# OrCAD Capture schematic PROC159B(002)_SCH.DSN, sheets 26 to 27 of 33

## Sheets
26 16. SOC-IO Interfaces: size C; title: SOC-IO Interfaces
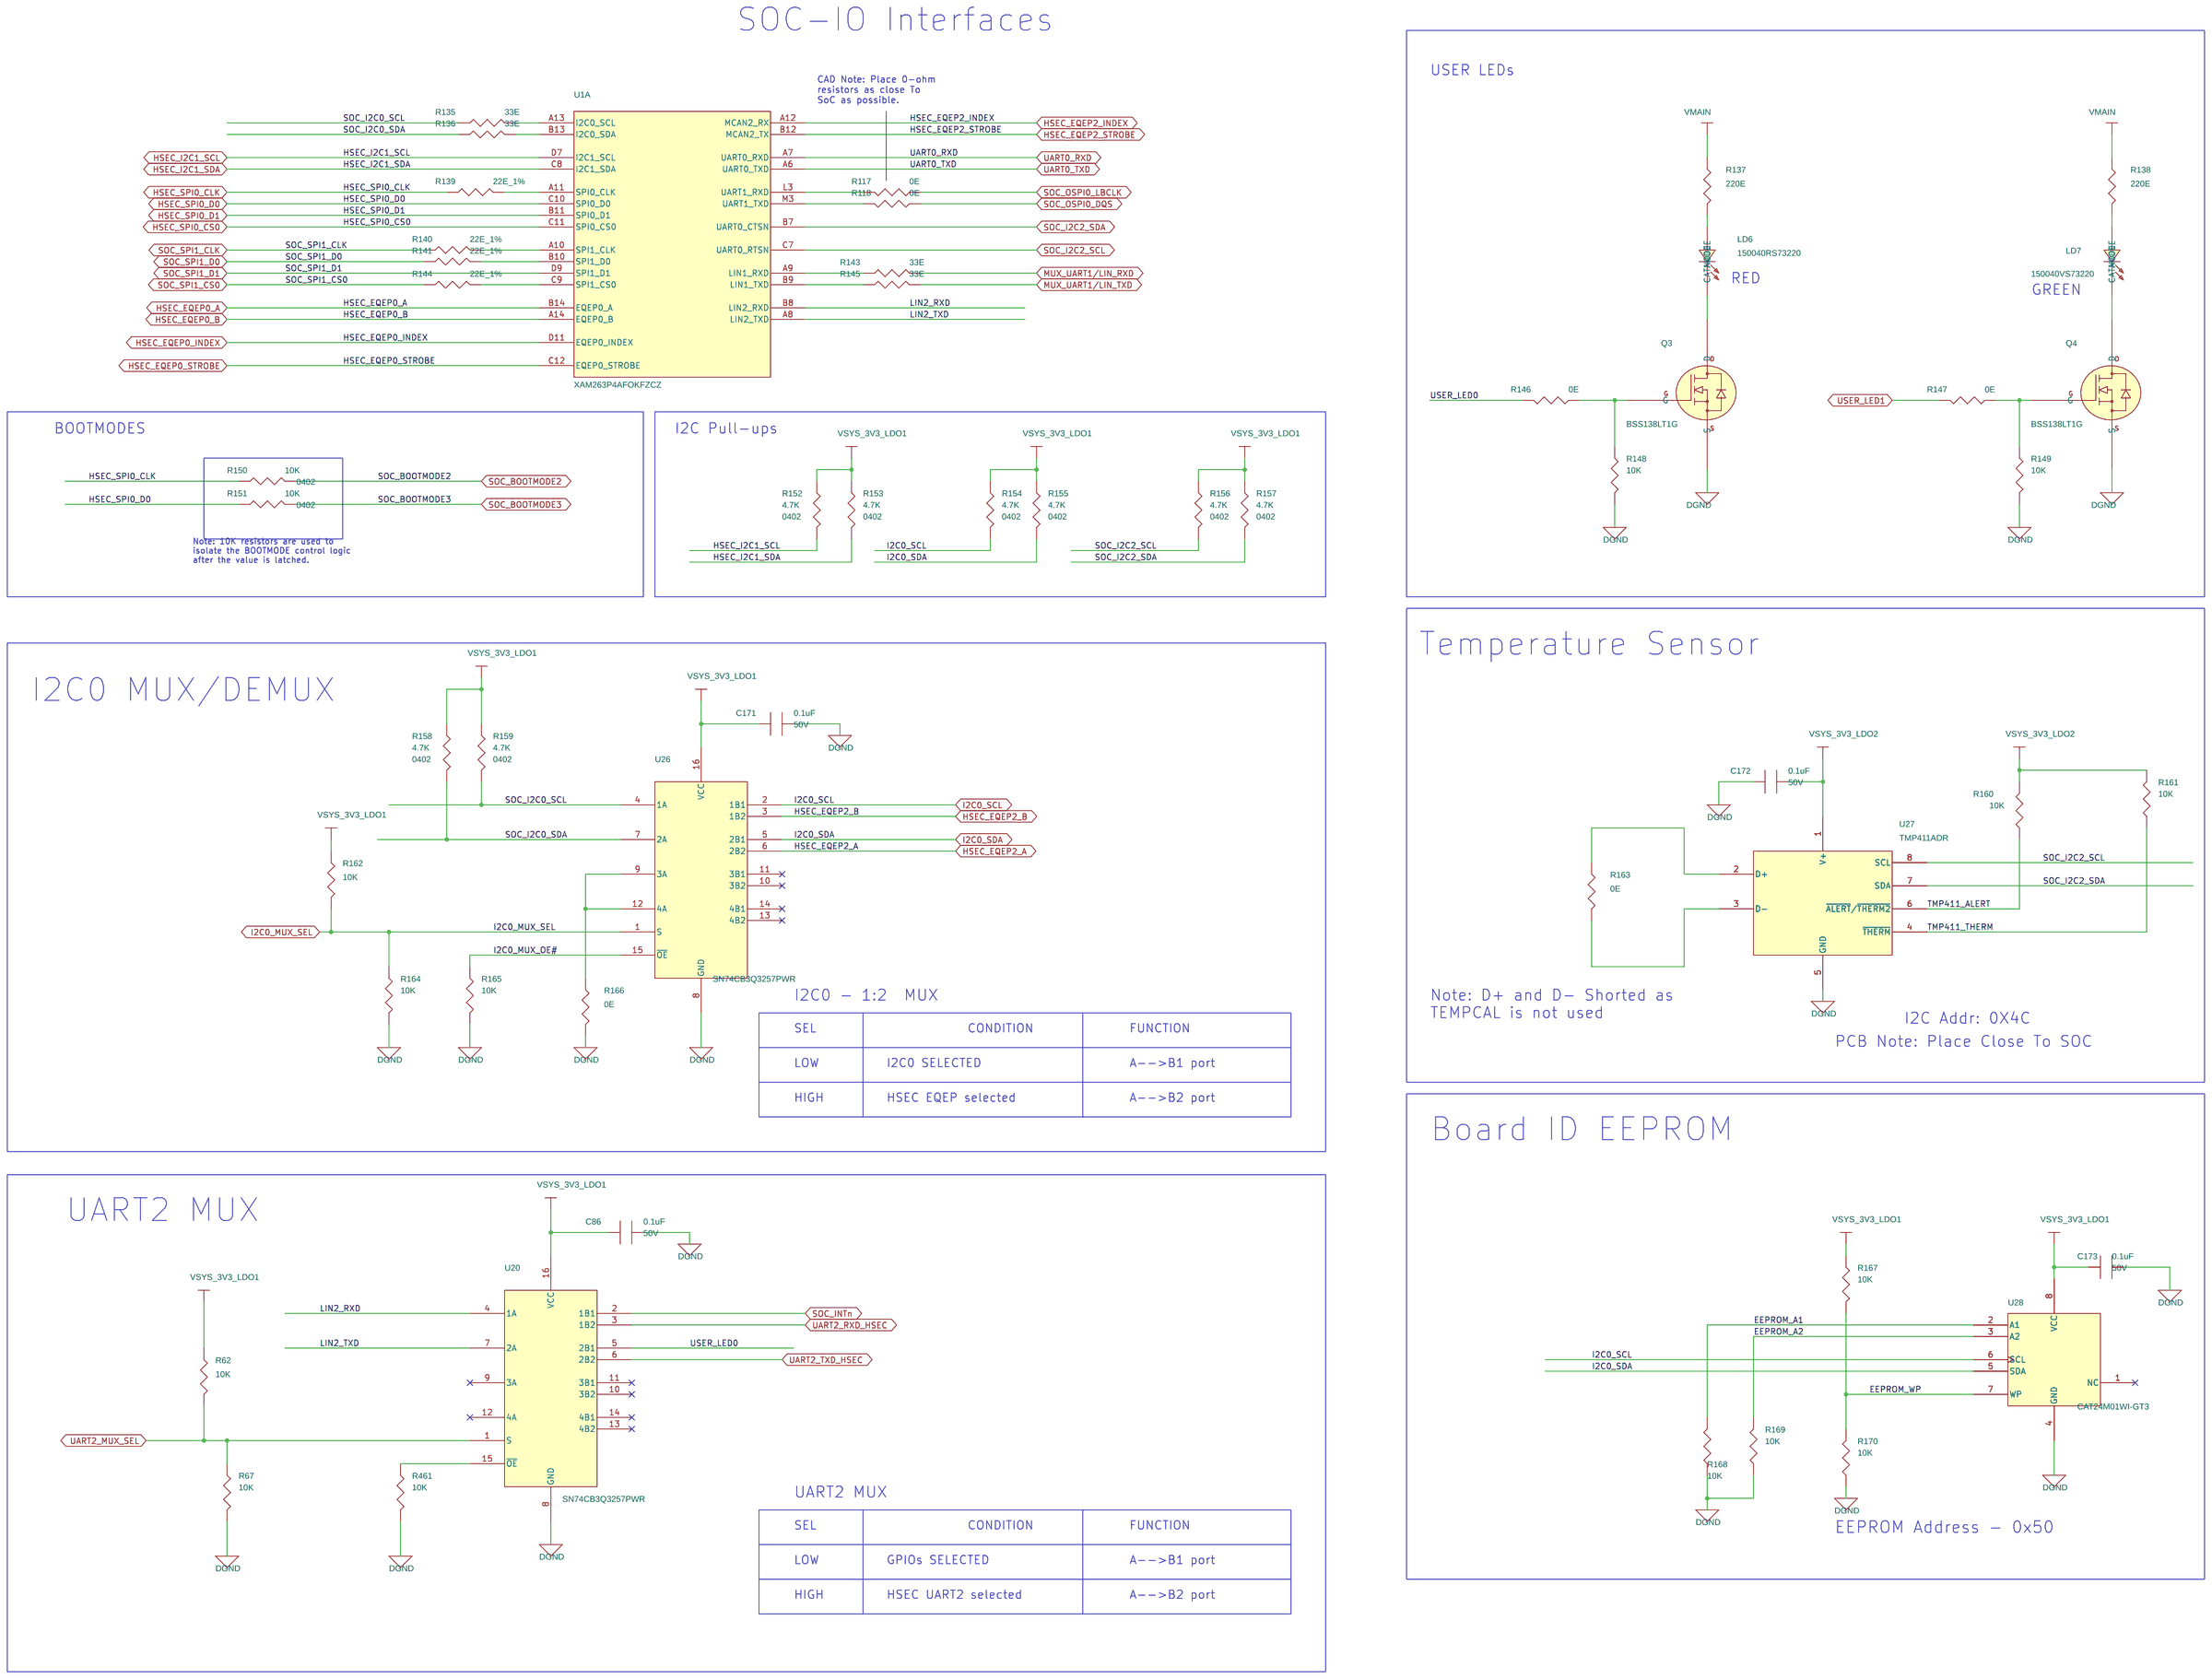
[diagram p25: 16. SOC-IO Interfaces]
27 17. SOC-JTAG, RESET and CLK: size C; title: SOC JTAG, RESET and CLKS
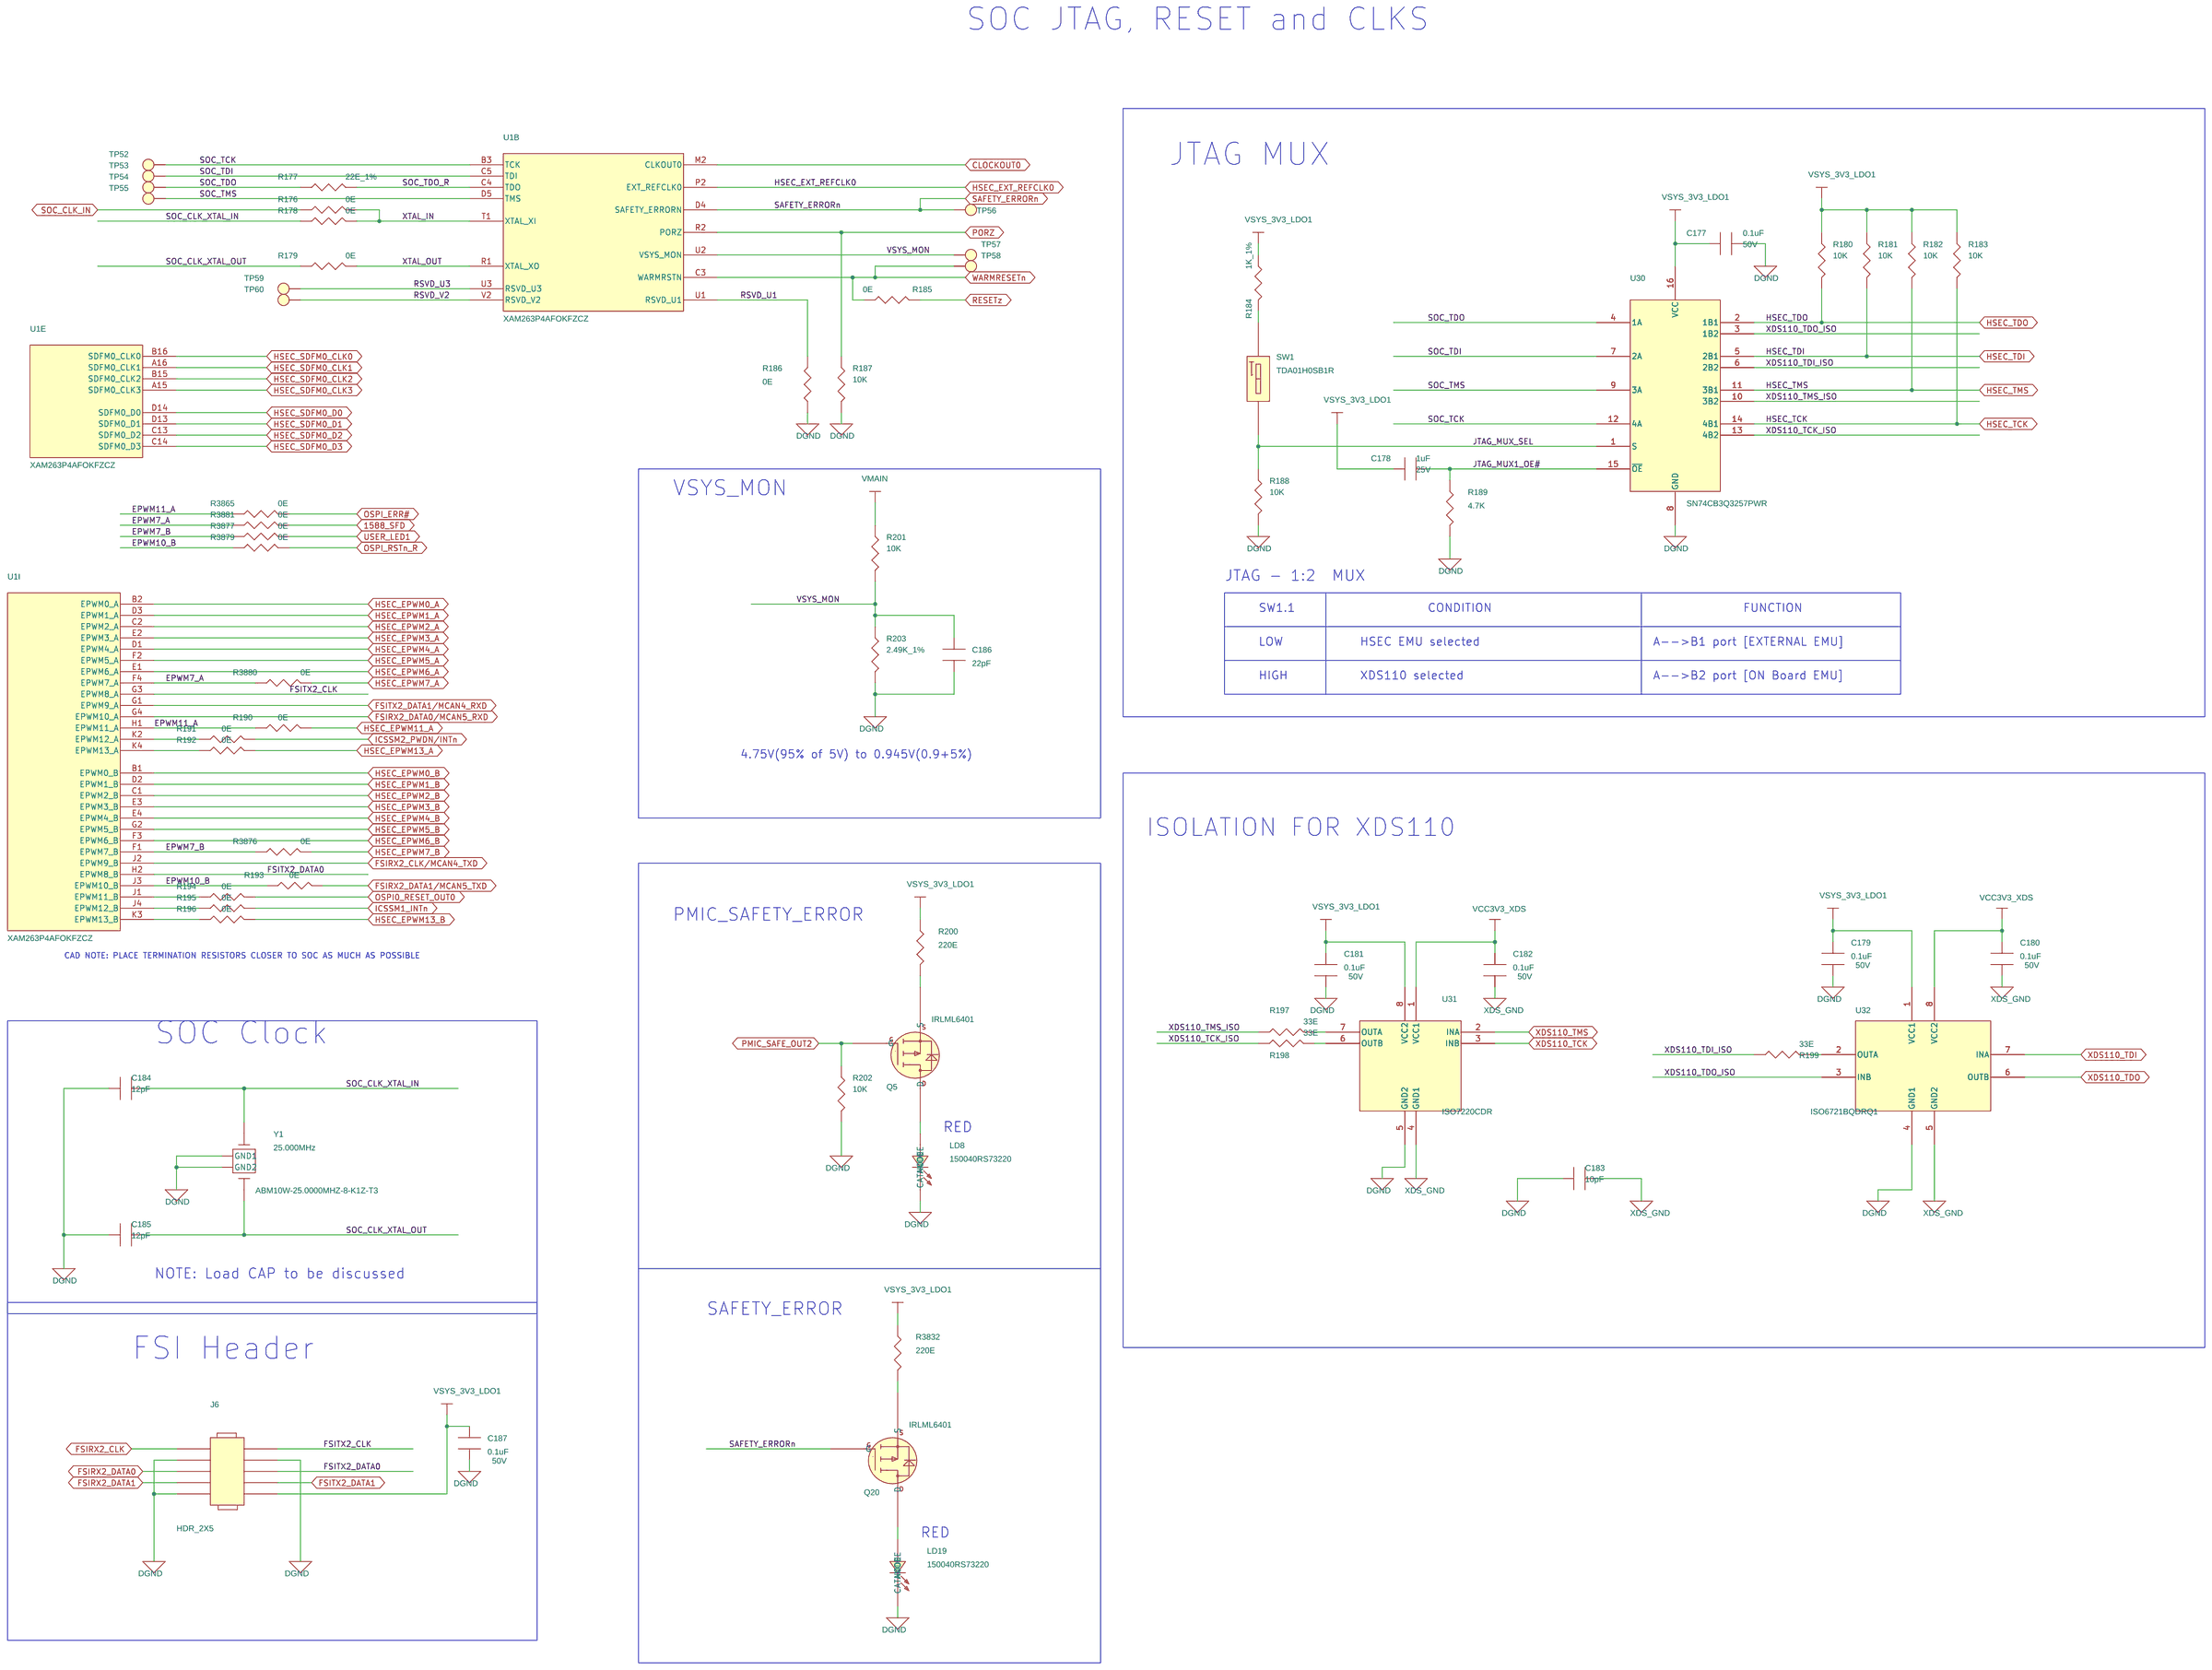
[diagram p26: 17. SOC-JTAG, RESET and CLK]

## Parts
sheet 16. SOC-IO Interfaces
C86  0.1uF  [CAP0402_0-75]
C171  0.1uF  [CAP0402_0-75]
C172  0.1uF  [CAP0402_0-75]
C173  0.1uF  [CAP0402_0-75]
LD6  150040RS73220  [LED_150040GS73220_40X20_SMD_0-4]
LD7  150040VS73220  [LED_150040GS73220_40X20_SMD_0-4]
Q3  BSS138LT1G  [SOT23-123_1-2]
Q4  BSS138LT1G  [SOT23-123_1-2]
R62  10K  [RES0402_0-5]
R67  10K  [RES0402_0-5]
R117  0E  [RES0402_0-5]
R118  0E  [RES0402_0-5]
R135  33E  [RES0402_0-5]
R136  33E  [RES0402_0-5]
R137  220E  [RES0402_0-5]
R138  220E  [RES0402_0-5]
R139  22E_1%  [RES0402_0-5]
R140  22E_1%  [RES0402_0-5]
R141  22E_1%  [RES0402_0-5]
R143  33E  [RES0402_0-5]
R144  22E_1%  [RES0402_0-5]
R145  33E  [RES0402_0-5]
R146  0E  [RES0402_0-5]
R147  0E  [RES0402_0-5]
R148  10K  [RES0402_0-5]
R149  10K  [RES0402_0-5]
R150  10K  [RES0402_0-5]
R151  10K  [RES0402_0-5]
R152  4.7K  [RES0402_0-5]
R153  4.7K  [RES0402_0-5]
R154  4.7K  [RES0402_0-5]
R155  4.7K  [RES0402_0-5]
R156  4.7K  [RES0402_0-5]
R157  4.7K  [RES0402_0-5]
R158  4.7K  [RES0402_0-5]
R159  4.7K  [RES0402_0-5]
R160  10K  [RES0402_0-5]
R161  10K  [RES0402_0-5]
R162  10K  [RES0402_0-5]
R163  0E  [RES0402_0-5]
R164  10K  [RES0402_0-5]
R165  10K  [RES0402_0-5]
R166  0E  [RES0402_0-5]
R167  10K  [RES0402_0-5]
R168  10K  [RES0402_0-5]
R169  10K  [RES0402_0-5]
R170  10K  [RES0402_0-5]
R461  10K  [RES0402_0-5]
U20  SN74CB3Q3257PWR  [TSSOP16_25-59_205X180]
U26  SN74CB3Q3257PWR  [TSSOP16_25-59_205X180]
U27  TMP411ADR  [SOIC8_1-8]
U28  CAT24M01WI-GT3  [SOIC8_1-8]
sheet 17. SOC-JTAG, RESET and CLK
C177  0.1uF  [CAP0402_0-75]
C178  1uF  [CAP0402_0-75]
C179  0.1uF  [CAP0402_0-75]
C180  0.1uF  [CAP0402_0-75]
C181  0.1uF  [CAP0402_0-75]
C182  0.1uF  [CAP0402_0-75]
C183  10pF  [CAP1812_1-25]
C184  12pF  [CAP0402_0-75]
C185  12pF  [CAP0402_0-75]
C186  22pF  [CAP0201_0-5]
C187  0.1uF  [CAP0402_0-75]
J6  HDR_2X5  [HDR_2X5_61301021121_S_T_8-6]
LD8  150040RS73220  [LED_150040GS73220_40X20_SMD_0-4]
LD19  150040RS73220  [LED_150040GS73220_40X20_SMD_0-4]
Q5  IRLML6401  [TO_SOT23-123]
Q20  IRLML6401  [TO_SOT23-123]
R176  0E  [RES0402_0-5]
R177  22E_1%  [RES0402_0-5]
R178  0E  [RES0402_0-5]
R179  0E  [RES0402_0-5]
R180  10K  [RES0402_0-5]
R181  10K  [RES0402_0-5]
R182  10K  [RES0402_0-5]
R183  10K  [RES0402_0-5]
R184  1K_1%  [RES0402_0-5]
R185  0E  [RES0402_0-5]
R186  0E  [RES0402_0-5]
R187  10K  [RES0402_0-5]
R188  10K  [RES0402_0-5]
R189  4.7K  [RES0402_0-5]
R190  0E  [RES0402_0-5]
R191  0E  [RES0402_0-5]
R192  0E  [RES0402_0-5]
R193  0E  [RES0402_0-5]
R194  0E  [RES0402_0-5]
R195  0E  [RES0402_0-5]
R196  0E  [RES0402_0-5]
R197  33E  [RES0402_0-5]
R198  33E  [RES0402_0-5]
R199  33E  [RES0402_0-5]
R200  220E  [RES0402_0-5]
R201  10K  [RES0402_0-5]
R202  10K  [RES0402_0-5]
R203  2.49K_1%  [RES0402_0-5]
R3832  220E  [RES0402_0-5]
R3865  0E  [RES0402_0-5]
R3876  0E  [RES0402_0-5]
R3877  0E  [RES0402_0-5]
R3879  0E  [RES0402_0-5]
R3880  0E  [RES0402_0-5]
R3881  0E  [RES0402_0-5]
SW1  TDA01H0SB1R  [SW_TDA01H0S_240X90_SMD_2-3]
TP52  TP40_SMD  [TP40_SMD]
TP53  TP40_SMD  [TP40_SMD]
TP54  TP40_SMD  [TP40_SMD]
TP55  TP40_SMD  [TP40_SMD]
TP56  TP40_SMD  [TP40_SMD]
TP57  TP40_SMD  [TP40_SMD]
TP58  TP40_SMD  [TP40_SMD]
TP59  TP40_SMD  [TP40_SMD]
TP60  TP40_SMD  [TP40_SMD]
U30  SN74CB3Q3257PWR  [TSSOP16_25-59_205X180]
U31  ISO7220CDR  [SOIC8]
U32  ISO6721BQDRQ1  [SOIC8_1-8]
Y1  25.000MHz  [XTAL4_ABM10W_100X80_SMD_0-6]
sheet 19. SOC-ICSS DP8386(Indust)
U1  XAM263P4AFOKFZCZ  [BGA324_31-49_590X590_1-4]  (sections A,B,C,D,E,F,G,H,I,J,K,L,M)

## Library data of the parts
C86 C171 C172 C177 C179-C182 C187 = CAP: CAP CERAMIC 0.1uF 50V 10% X7R 0402; Automotive Alternate_mfr_name: TDK; Automotive Alternate_mfr_part_number: CGA2B3X7R1H104K050BB; Chkd/date: MANIRAJA/261020; Crtd /date: ALVY/211020; Custom_Duty: 15%; Customs_HS_Code: 85322990; Direct Alternate_mfr_name: TDK; Direct Alternate_mfr_part_number: C1005X7R1H104K050BE; Distributor_name: DIGIKEY; Distributor_part_number: 490-10700-1-ND; Footprint Path: Y:\MIS_DATABASE\Library\ALTIUM_TOOL\PCB_FOOTPRINTS\Altium_Footprint_Lib.PcbLib; Height: 0.55MM; Library Path: Y:\MIS_DATABASE\Library\ALTIUM_TOOL\SCHEMATICS_PARTS\MS_DISCRETE_Library.schlib; Mfr_name: MURATA; Mfr_part_number: GRM155R71H104KE14D; Mistral Part No: 120011100014-R; Package: 0402; Part_type: CAPACITORS\CERAMIC; Project: J7_CP; RoHS: RoHS; Temperature: -55°C+125°C; Tolerance: 10%; Voltage: 50V; Wattage: NA; Weight: 3.1mg; Datasheet: Y:\MIS_DATABASE\DATASHEETS\CAPACITORS\GRM155R71H104KE14.PDF
C173 = CAP: CAP CERAMIC 0.1uF 50V 10% X7R 0402; Automotive Alternate_mfr_name: TDK; Automotive Alternate_mfr_part_number: CGA2B1X7R1C104K050BC; Chkd/date: MANIRAJA/261020; Crtd /date: ALVY/211020; Custom_Duty: 15%; Customs_HS_Code: 85322990; Direct Alternate_mfr_name: MURATA; Direct Alternate_mfr_part_number: GCM155R71C104JA55D; Distributor_name: DIGIKEY; Distributor_part_number: 490-10700-1-ND; Footprint Path: Y:\MIS_DATABASE\Library\ALTIUM_TOOL\PCB_FOOTPRINTS\Altium_Footprint_Lib.PcbLib; Height: 0.55MM; Library Path: Y:\MIS_DATABASE\Library\ALTIUM_TOOL\SCHEMATICS_PARTS\MS_DISCRETE_Library.schlib; Mfr_name: MURATA; Mfr_part_number: GRM155R71H104KE14D; Mistral Part No: 120011100014-R; Package: 0402; Part_type: CAPACITORS\CERAMIC; Project: J7_CP; RoHS: RoHS; Temperature: -55°C+125°C; Tolerance: 10%; Voltage: 50V; Wattage: NA; Weight: 3.1mg; Datasheet: Y:\MIS_DATABASE\DATASHEETS\CAPACITORS\GRM155R71H104KE14.PDF
LD6 LD8 LD19 = DIODE_LED: DIODE LED RED SMD; Chkd/date: MANIRAJA/100920; Crtd /date: ALVY/100920; Custom_Duty: 24%; Customs_HS_Code: 85439000; Distributor_name: DIGIKEY; Distributor_part_number: 732-13422-1-ND; Footprint Path: Y:\MIS_DATABASE\Library\ALTIUM_TOOL\PCB_FOOTPRINTS\Altium_Footprint_Lib.PcbLib; Height: 0.35MM; Library Path: Y:\MIS_DATABASE\Library\ALTIUM_TOOL\SCHEMATICS_PARTS\MS_OPTO_Library.schlib; Mfr_name: WURTH ELECTRONICS; Mistral Part No: 130020090020-R; Package: SMD; Part_type: OPTO\LED; Project: AM64X_SKEVM; RoHS: RoHS; Temperature: -40°C+85°C; Tolerance: NA; Voltage: NA; Wattage: NA; Weight: 29.3mg; Datasheet: Y:\MIS_DATABASE\DATASHEETS\DISCRETES\LEDS\150040RS73220.PDF
LD7 = DIODE_LED: DIODE LED BRIGHT GREEN SMD; Chkd/date: MANIRAJA/261120; Crtd /date: ALVY/261120; Custom_Duty: 24%; Customs_HS_Code: 85439000; Distributor_name: DIGIKEY; Distributor_part_number: 732-13425-1-ND; Footprint Path: Y:\MIS_DATABASE\Library\ALTIUM_TOOL\PCB_FOOTPRINTS\Altium_Footprint_Lib.PcbLib; Height: 0.35MM; Library Path: Y:\MIS_DATABASE\Library\ALTIUM_TOOL\SCHEMATICS_PARTS\MS_OPTO_Library.schlib; Mfr_name: WURTH ELECTRONIK; Mistral Part No: 130020110071-R; Package: SMD; Part_type: OPTO\LED; Project: AM64X_SKEVM; RoHS: RoHS; Temperature: -40°C+85°C; Tolerance: NA; Voltage: NA; Wattage: NA; Weight: 29.3mg; Datasheet: Y:\MIS_DATABASE\DATASHEETS\DISCRETES\LEDS\150040VS73220.PDF
Q3 Q4 = MOSFET_BSS138W: IC MOSFET N-CHANNEL 50V 200mA SOT23-3; Chkd/date: MANIRAJA/250219; Crtd /date: JEBRAN/060416; Custom_Duty: 15%; Customs_HS_Code: 85423100; Distributor_name: DIGIKEY; Distributor_part_number: BSS138LT1GOSCT-ND; Footprint Path: Y:\MIS_DATABASE\Library\ALTIUM_TOOL\PCB_FOOTPRINTS\Altium_Footprint_Lib.PcbLib; Height: 1.11MM; Library Path: Y:\MIS_DATABASE\Library\ALTIUM_TOOL\SCHEMATICS_PARTS\MS_MOSFET_Library.schlib; Mfr_name: ON SEMICONDUCTOR; Mistral Part No: 142016040001-R; Package: SOT23-3; Part_type: ICS\POWER\MOSFET; Project: LRDE_ABCM; RoHS: RoHS; Temperature: -55°C+150°C; Tolerance: NA; Voltage: NA; Wattage: NA; Weight: 8mg; Datasheet: Y:\MIS_DATABASE\DATASHEETS\DISCRETES\TRANSISTORS_FETS\BSS138LT1G.PDF
R62 R150 R151 R162 R168-R170 = RESISTOR: RES 10K 1/16W 5% 0402; Chkd/date: VASANTHA/061216; Crtd /date: MAZHAR/230805; Custom_Duty: 15%; Customs_HS_Code: 85332119; Distributor_name: DIGIKEY; Distributor_part_number: 311-10KJRCT-ND; Footprint Path: Y:\MIS_DATABASE\Library\ALTIUM_TOOL\PCB_FOOTPRINTS\Altium_Footprint_Lib.PcbLib; Height: 0.40MM; Library Path: Y:\MIS_DATABASE\Library\ALTIUM_TOOL\SCHEMATICS_PARTS\MS_DISCRETE_Library.schlib; Mfr_name: YAGEO AMERICA; Mfr_part_number: RC0402JR-0710KL; Mistral Part No: 110011060021-R; Package: 0402; Part_type: RESISTORS\FIXED; Project: HSE; RoHS: RoHS; Temperature: -55°C+155°C; Tolerance: 5%; Voltage: NA; Wattage: 1/16W; Weight: 0.65mg; Datasheet: Y:\MIS_DATABASE\DATASHEETS\RESISTORS\RCXXXXL-SER_MAR18.PDF
R67 R148 R149 R160 R161 R164 R165 R167 R180-R183 R187 R188 R201 R202 R461 = RESISTOR: RES 10K 1/16W 5% 0402; Assembly_Instruction: DNI; Chkd/date: VASANTHA/061216; Crtd /date: MAZHAR/230805; Custom_Duty: 15%; Customs_HS_Code: 85332119; Distributor_name: DIGIKEY; Distributor_part_number: 311-10KJRCT-ND; Footprint Path: Y:\MIS_DATABASE\Library\ALTIUM_TOOL\PCB_FOOTPRINTS\Altium_Footprint_Lib.PcbLib; Height: 0.40MM; Library Path: Y:\MIS_DATABASE\Library\ALTIUM_TOOL\SCHEMATICS_PARTS\MS_DISCRETE_Library.schlib; Mfr_name: YAGEO AMERICA; Mfr_part_number: RC0402JR-0710KL; Mistral Part No: 110011060021-R; Package: 0402; Part_type: RESISTORS\FIXED; Project: HSE; RoHS: RoHS; Temperature: -55°C+155°C; Tolerance: 5%; Voltage: NA; Wattage: 1/16W; Weight: 0.65mg; Datasheet: Y:\MIS_DATABASE\DATASHEETS\RESISTORS\RCXXXXL-SER_MAR18.PDF
R117 R118 R146 R147 R163 R166 R190-R196 R3865 R3876 R3877 R3879-R3881 = RESISTOR: RES 0E 1/10W JUMPER 0402; Chkd/date: VASANTHA/061216; Crtd /date: NAVEED/201014; Custom_Duty: 15%; Customs_HS_Code: 85332119; Distributor_name: DIGIKEY; Distributor_part_number: P0.0JCT-ND; Footprint Path: Y:\MIS_DATABASE\Library\ALTIUM_TOOL\PCB_FOOTPRINTS\Altium_Footprint_Lib.PcbLib; Height: 0.40MM; IBISSP_MODLES: VALUE REPEATING 2 TIME; Library Path: Y:\MIS_DATABASE\Library\ALTIUM_TOOL\SCHEMATICS_PARTS\MS_DISCRETE_Library.schlib; Mfr_name: PANASONIC-ECG; Mfr_part_number: ERJ-2GE0R00X; Mistral Part No: 110018030052-R; Package: 0402; Part_type: RESISTORS\FIXED; Project: AEGIS POM; RoHS: RoHS; Temperature: -55°C+155°C; Tolerance: NA; Voltage: NA; Wattage: 1/10W; Weight: 0.8mg; Datasheet: Y:\MIS_DATABASE\DATASHEETS\RESISTORS\PAN-ERJSER_NOV17.PDF
R135 R136 R143 R145 R197-R199 = RESISTOR: RES 33E 1/10W 5% 0402; Chkd/date: VASANTHA/201216; Crtd /date: GEETHA/190406; Custom_Duty: 15%; Customs_HS_Code: 85332119; Distributor_name: DIGIKEY; Distributor_part_number: P33JCT-ND; Footprint Path: Y:\MIS_DATABASE\Library\ALTIUM_TOOL\PCB_FOOTPRINTS\Altium_Footprint_Lib.PcbLib; Height: 0.40MM; Library Path: Y:\MIS_DATABASE\Library\ALTIUM_TOOL\SCHEMATICS_PARTS\MS_DISCRETE_Library.schlib; Mfr_name: PANASONIC-ECG; Mfr_part_number: ERJ-2GEJ330X; Mistral Part No: 110009030699-R; Package: 0402; Part_type: RESISTORS\FIXED; Project: RED EYE; RoHS: RoHS; Temperature: -55°C+155°C; Tolerance: 5%; Voltage: NA; Wattage: 1/10W; Weight: 0.8mg; Datasheet: Y:\MIS_DATABASE\DATASHEETS\RESISTORS\PAN-ERJSER_NOV17.PDF
R137 R138 R200 R3832 = RESISTOR: RES 220E 1/10W 5% 0402; Chkd/date: VASANTHA/291216; Crtd /date: GEETHA/260406; Custom_Duty: 15%; Customs_HS_Code: 85332119; Distributor_name: DIGIKEY; Distributor_part_number: P220JCT-ND; Footprint Path: Y:\MIS_DATABASE\Library\ALTIUM_TOOL\PCB_FOOTPRINTS\Altium_Footprint_Lib.PcbLib; Height: 0.40MM; Library Path: Y:\MIS_DATABASE\Library\ALTIUM_TOOL\SCHEMATICS_PARTS\MS_DISCRETE_Library.schlib; Mfr_name: PANASONIC-ECG; Mfr_part_number: ERJ-2GEJ221X; Mistral Part No: 110009030506-R; Package: 0402; Part_type: RESISTORS\FIXED; Project: RED EYE; RoHS: RoHS; Temperature: -55°C+155°C; Tolerance: 5%; Voltage: NA; Wattage: 1/10W; Weight: 0.8mg; Datasheet: Y:\MIS_DATABASE\DATASHEETS\RESISTORS\PAN-ERJSER_NOV17.PDF
R139-R141 R144 R177 = RESISTOR: RES 22E 1/10W 1% 0402; Chkd/date: MANIRAJA/270319; Crtd /date: MANIRAJA/270319; Custom_Duty: 15%; Customs_HS_Code: 85332119; Distributor_name: DIGIKEY; Distributor_part_number: P22.0LCT-ND; Footprint Path: Y:\MIS_DATABASE\Library\ALTIUM_TOOL\PCB_FOOTPRINTS\Altium_Footprint_Lib.PcbLib; Height: 0.40MM; Library Path: Y:\MIS_DATABASE\Library\ALTIUM_TOOL\SCHEMATICS_PARTS\MS_DISCRETE_Library.schlib; Mfr_name: PANASONIC-ECG; Mfr_part_number: ERJ-2RKF22R0X; Mistral Part No: 110019040025-R; Package: 0402; Part_type: RESISTORS\FIXED; Project: V8TS; RoHS: RoHS; Temperature: -55°C+155°C; Tolerance: 1%; Voltage: NA; Wattage: 1/10W; Weight: 0.8mg; Datasheet: Y:\MIS_DATABASE\DATASHEETS\RESISTORS\PAN-ERJSER_NOV17.PDF
R152-R159 R189 = RESISTOR: RES 4.7K 1/16W 5% 0402; Chkd/date: VASANTHA/130516; Crtd /date: VASANTHA/130516; Custom_Duty: 15%; Customs_HS_Code: 85332119; Distributor_name: DIGIKEY; Distributor_part_number: 311-4.7KJRCT-ND; Footprint Path: Y:\MIS_DATABASE\Library\ALTIUM_TOOL\PCB_FOOTPRINTS\Altium_Footprint_Lib.PcbLib; Height: 0.40MM; Library Path: Y:\MIS_DATABASE\Library\ALTIUM_TOOL\SCHEMATICS_PARTS\MS_DISCRETE_Library.schlib; Mfr_name: YAGEO AMERICA; Mfr_part_number: RC0402JR-074K7L; Mistral Part No: 110011060001-R; Package: 0402; Part_type: RESISTORS\FIXED; Project: TMDXCSK368; RoHS: RoHS; Temperature: -55°C+155°C; Tolerance: 5%; Voltage: NA; Wattage: 1/16W; Weight: 0.65mg; Datasheet: Y:\MIS_DATABASE\DATASHEETS\RESISTORS\RCXXXXL-SER_MAR18.PDF
U20 U26 U30 = SN74CB3Q3257PWR_TSSOP16: IC 4BIT 1-OF-2 FET MULTIPLEXER/DEMULTIPLEXER TSSOP16; Chkd/date: SUHAS/251010; Crtd /date: USMAN/060109; Custom_Duty: 15%; Customs_HS_Code: 85423100; Distributor_name: DIGIKEY; Distributor_part_number: 296-19138-1-ND; Height: 1.20MM; Mfr_name: TEXAS INSTRUMENTS; Mistral Part No: 141009030117-R; Package: TSSOP16; Part_type: ICS\DIGITAL\COMBINATIONAL; Project: OMAP_EVM; RoHS: Sb/ Br FREE; Temperature: -40°C+85°C; Datasheet: Y:\MIS_DATABASE\DATASHEETS\ICS\DIGITAL\COMBINATIONAL\SN74CB3Q3257.PDF
U27 = TMP411ADR_SOIC8: IC REMOTE AND LOCAL TEMPERATURE SENSOR WITH N-FACTOR AND SERIES RESISTANCE CORRECTION SOIC8; Chkd/date: ALVY/070521; Crtd /date: MANIRAJA/070521; Custom_Duty: 15%; Customs_HS_Code: 85423100; Distributor_name: DIGIKEY; Distributor_part_number: 296-47859-2-ND; Footprint Path: Y:\MIS_DATABASE\Library\ALTIUM_TOOL\PCB_FOOTPRINTS\Altium_Footprint_Lib.PcbLib; Height: 1.75MM; Library Path: Y:\MIS_DATABASE\Library\ALTIUM_TOOL\SCHEMATICS_PARTS\MS_COMBINATIONAL_Library.schlib; Mfr_name: TEXAS INSTRUMENTS; Mistral Part No: 141021050005-R; Package: SOIC8; Part_type: ICS\DIGITAL\PERIPHERAL; Project: AM263x_CC; RoHS: RoHS; Temperature: -40°C+125°C; Tolerance: NA; Voltage: NA; Wattage: NA; Weight: 76mg; Datasheet: Y:\MIS_DATABASE\DATASHEETS\ICS\DIGITAL\PERIPHERAL\TMP411XXX.PDF
U28 = AT24HC04B-TH-B_TSSOP8: IC 1Mb I2C SERIAL EEPROM SOIC8; Chkd/date: ALVY/230621; Crtd /date: ALVY/230621; Custom_Duty: 15%; Customs_HS_Code: 85423100; Distributor_name: DIGIKEY; Distributor_part_number: CAT24M01WI-GT3OSCT-ND; Footprint Path: Y:\MIS_DATABASE\Library\ALTIUM_TOOL\PCB_FOOTPRINTS\Altium_Footprint_Lib.PcbLib; Height: 1.75MM; Library Path: Y:\MIS_DATABASE\Library\ALTIUM_TOOL\SCHEMATICS_PARTS\MS_MISCMEMORY_Library.schlib; Mfr_name: ON SEMICONDUCTOR; Mistral Part No: 141121060004-R; Package: SOIC8; Part_type: ICS\DIGITAL\MEMORY; Project: AM263x_CC; RoHS: RoHS; Temperature: -40°C+85°C; Tolerance: NA; Voltage: NA; Wattage: NA; Weight: 540mg; Datasheet: Y:\MIS_DATABASE\DATASHEETS\ICS\MEMORY\CAT24M01.PDF
C178 = CAP: CAP CERAMIC 1uF 25V 10% X6S 0402; Automotive Alternate_mfr_name: TAIYO YUDEN; Automotive Alternate_mfr_part_number: EMK105BJ105KVHF; Chkd/date: MANIRAJA/140518; Crtd /date: ALVY/140518; Custom_Duty: 15%; Customs_HS_Code: 85322990; Direct Alternate_mfr_name: YAGEO AMERICA; Direct Alternate_mfr_part_number: CC0402KRX5R7BB105; Distributor_name: DIGIKEY; Distributor_part_number: 490-10014-1-ND; Footprint Path: Y:\MIS_DATABASE\Library\ALTIUM_TOOL\PCB_FOOTPRINTS\Altium_Footprint_Lib.PcbLib; Height: 0.60MM; Library Path: Y:\MIS_DATABASE\Library\ALTIUM_TOOL\SCHEMATICS_PARTS\MS_DISCRETE_Library.schlib; Mfr_name: MURATA; Mfr_part_number: GRM155C81E105KE11D; Mistral Part No: 120018050004-R; Package: 0402; Part_type: CAPACITORS\CERAMIC; Project: TI_SVB_MAXWELL_DUT; RoHS: RoHS; Temperature: -55°C+105°C; Tolerance: 10%; Voltage: 25V; Wattage: NA; Weight: 6mg; Datasheet: Y:\MIS_DATABASE\DATASHEETS\CAPACITORS\GRM155C81E105KE11X.PDF
C183 = CAP: CAP CERAMIC 10pF 3KV 5% C0G(NP0) 1812; Chkd/date: ALVY/080621; Crtd /date: MANIRAJA/080621; Custom_Duty: 15%; Customs_HS_Code: 85322990; Distributor_name: DIGIKEY; Distributor_part_number: 399-7113-1-ND; Footprint Path: Y:\MIS_DATABASE\Library\ALTIUM_TOOL\PCB_FOOTPRINTS\Altium_Footprint_Lib.PcbLib; Height: 1.10MM; Library Path: Y:\MIS_DATABASE\Library\ALTIUM_TOOL\SCHEMATICS_PARTS\MS_DISCRETE_Library.schlib; Mfr_name: KEMET; Mfr_part_number: C1812C100JHGACTU; Mistral Part No: 120021060004-R; Package: 1812; Part_type: CAPACITORS\CERAMIC; Project: TI_AM263X_CC; RoHS: RoHS; Temperature: -55°C+125°C; Tolerance: 5%; Voltage: 3KV; Wattage: NA; Weight: 110mg; Datasheet: Y:\MIS_DATABASE\DATASHEETS\CAPACITORS\KEMET-C-C0G_HV.PDF
C184 C185 = CAP: CAP CERAMIC 12pF 50V 5% HI-Q C0G(NP0) 0402; Chkd/date: MANIRAJA/020419; Crtd /date: MANIRAJA/020419; Custom_Duty: 15%; Customs_HS_Code: 85322990; Distributor_name: DIGIKEY; Distributor_part_number: 490-3115-1-ND; Footprint Path: Y:\MIS_DATABASE\Library\ALTIUM_TOOL\PCB_FOOTPRINTS\Altium_Footprint_Lib.PcbLib; Height: 0.55MM; Library Path: Y:\MIS_DATABASE\Library\ALTIUM_TOOL\SCHEMATICS_PARTS\MS_DISCRETE_Library.schlib; Mfr_name: MURATA; Mfr_part_number: GJM1555C1H120JB01D; Mistral Part No: 120019040031-R; Package: 0402; Part_type: CAPACITORS\CERAMIC; Project: EPDA_CORE; RoHS: RoHS; Temperature: -55°C+125°C; Tolerance: 5%; Voltage: 50V; Wattage: NA; Weight: 0.65mg; Datasheet: Y:\MIS_DATABASE\DATASHEETS\CAPACITORS\GJM1555C1H120JB01.PDF
C186 = CAP: CAP CERAMIC 22pF 25V 1% C0G(NP0) 0201; Chkd/date: MANIRAJA/270721; Crtd /date: ALVY/260721; Custom_Duty: 15%; Customs_HS_Code: 85322990; Distributor_name: DIGIKEY; Distributor_part_number: 490-14545-1-ND; Footprint Path: Y:\MIS_DATABASE\Library\ALTIUM_TOOL\PCB_FOOTPRINTS\Altium_Footprint_Lib.PcbLib; Height: 0.33MM; Library Path: Y:\MIS_DATABASE\Library\ALTIUM_TOOL\SCHEMATICS_PARTS\MS_DISCRETE_Library.schlib; Mfr_name: MURATA; Mfr_part_number: GRM0335C1E220FA01D; Mistral Part No: 120021070019-R; Package: 0201; Part_type: CAPACITORS\CERAMIC; Project: TI_AM335x SK_BRD; RoHS: RoHS; Temperature: -55°C+125°C; Tolerance: 1%; Voltage: 25V; Wattage: NA; Weight: 0.33mg; Datasheet: Y:\MIS_DATABASE\DATASHEETS\CAPACITORS\GRM0335C1E220FA01.PDF
J6 = HEADER_5X2: CON HDR 2X5 2.54MM PITCH ST TH; Chkd/date: MANIRAJA/121120; Crtd /date: ALVY/111120; Custom_Duty: 24%; Customs_HS_Code: 85369090; Distributor_name: DIGIKEY; Distributor_part_number: 732-2672-ND; Footprint Path: Y:\MIS_DATABASE\Library\ALTIUM_TOOL\PCB_FOOTPRINTS\Altium_Footprint_Lib.PcbLib; Height: 8.54MM; Library Path: Y:\MIS_DATABASE\Library\ALTIUM_TOOL\SCHEMATICS_PARTS\MS_CONNECTOR_Library.schlib; Mfr_name: WURTH ELEKTRONIK; Mfr_part_number: 61301021121; Mistral Part No: 150020110011-R; Package: THRU-HOLE; Part_type: CONNECTOR\HEADERS; Project: TI_AM243x LP EVM; RoHS: RoHS; Temperature: -40°C+105°C; Tolerance: NA; Voltage: NA; Wattage: NA; Weight: 550mg; Datasheet: Y:\MIS_DATABASE\DATASHEETS\CONNECTORS\6130XX21121.PDF
Q5 Q20 = MOSFET_IRLML6401TR: TRANSISTOR MOSFET P-CHANNEL SOT23-3; Chkd/date: SHREESHAIL/020206; Crtd /date: MAZHAR/040505; Custom_Duty: 15%; Customs_HS_Code: 85412900; Distributor_name: DIGIKEY; Distributor_part_number: IRLML6401PBFCT-ND; Height: 1.11MM; Mfr_name: IRF; Mfr_part_number: IRLML6401TRPBF; Mistral Part No: 130009031213-P; Package: SOT23-3; Part_type: TRANSISTOR\MOSFET; Project: G4_SVGA; RoHS: Pb-Free; Temperature: -55°C+150°C; Tolerance: NA; Voltage: NA; Wattage: NA; Weight: NA; Datasheet: Y:\MIS_DATABASE\DATASHEETS\DISCRETES\TRANSISTORS_FETS\IRLML6401.PDF
R176 R178 R179 R185 R186 = RESISTOR: RES 0E 1/10W JUMPER 0402; Assembly_Instruction: DNI; Chkd/date: VASANTHA/061216; Crtd /date: NAVEED/201014; Custom_Duty: 15%; Customs_HS_Code: 85332119; Distributor_name: DIGIKEY; Distributor_part_number: P0.0JCT-ND; Footprint Path: Y:\MIS_DATABASE\Library\ALTIUM_TOOL\PCB_FOOTPRINTS\Altium_Footprint_Lib.PcbLib; Height: 0.40MM; IBISSP_MODLES: VALUE REPEATING 2 TIME; Library Path: Y:\MIS_DATABASE\Library\ALTIUM_TOOL\SCHEMATICS_PARTS\MS_DISCRETE_Library.schlib; Mfr_name: PANASONIC-ECG; Mfr_part_number: ERJ-2GE0R00X; Mistral Part No: 110018030052-R; Package: 0402; Part_type: RESISTORS\FIXED; Project: AEGIS POM; RoHS: RoHS; Temperature: -55°C+155°C; Tolerance: NA; Voltage: NA; Wattage: 1/10W; Weight: 0.8mg; Datasheet: Y:\MIS_DATABASE\DATASHEETS\RESISTORS\PAN-ERJSER_NOV17.PDF
R184 = RESISTOR: RES 1K 1/10W 1% 0402; Chkd/date: VASANTHA/281216; Crtd /date: MAZHAR/150506; Custom_Duty: 15%; Customs_HS_Code: 85332119; Distributor_name: DIGIKEY; Distributor_part_number: P1.00KLCT-ND; Footprint Path: Y:\MIS_DATABASE\Library\ALTIUM_TOOL\PCB_FOOTPRINTS\Altium_Footprint_Lib.PcbLib; Height: 0.40MM; Library Path: Y:\MIS_DATABASE\Library\ALTIUM_TOOL\SCHEMATICS_PARTS\MS_DISCRETE_Library.schlib; Mfr_name: PANASONIC-ECG; Mfr_part_number: ERJ-2RKF1001X; Mistral Part No: 110009030411-R; Package: 0402; Part_type: RESISTORS\FIXED; Project: VOCERA; RoHS: RoHS; Temperature: -55°C+155°C; Tolerance: 1%; Voltage: NA; Wattage: 1/10W; Weight: 0.8mg; Datasheet: Y:\MIS_DATABASE\DATASHEETS\RESISTORS\PAN-ERJSER_NOV17.PDF
R203 = RESISTOR: RES 2.49K 1/16W 1% 0402; Chkd/date: VASANTHA/050115; Crtd /date: USMAN/300709; Custom_Duty: 15%; Customs_HS_Code: 85332119; Distributor_name: DIGIKEY; Distributor_part_number: 541-2.49KLCT-ND; Footprint Path: Y:\MIS_DATABASE\Library\ALTIUM_TOOL\PCB_FOOTPRINTS\Altium_Footprint_Lib.PcbLib; Height: 0.40MM; Library Path: Y:\MIS_DATABASE\Library\ALTIUM_TOOL\SCHEMATICS_PARTS\MS_DISCRETE_Library.schlib; Mfr_name: VISHAY; Mfr_part_number: CRCW04022K49FKED; Mistral Part No: 110016050020-R; Package: 0402; Part_type: RESISTORS\FIXED; Project: VMEFMCD; RoHS: RoHS; Temperature: -55°C+155°C; Tolerance: 1%; Voltage: NA; Wattage: 1/16W; Weight: 0.65mg; Datasheet: Y:\MIS_DATABASE\DATASHEETS\RESISTORS\CRCW0603.PDF
SW1 = SW2_CHS-01TA: SWITCH SLIDE 1POS SPST SMD; Chkd/date: MANIRAJA/031018; Crtd /date: MANIRAJA/031018; Custom_Duty: 24%; Customs_HS_Code: 85369090; Distributor_name: DIGIKEY; Distributor_part_number: CKN10538CT-ND; Footprint Path: Y:\MIS_DATABASE\Library\ALTIUM_TOOL\PCB_FOOTPRINTS\Altium_Footprint_Lib.PcbLib; Height: 2.30MM; Library Path: Y:\MIS_DATABASE\Library\ALTIUM_TOOL\SCHEMATICS_PARTS\MS_SWITCH_Library.schlib; Mfr_name: CK; Mistral Part No: 130018100003-R; Package: SMD; Part_type: ELECTRO-MECHANICAL\SWITCH; Project: TI_60GHz-AOP; RoHS: RoHS; Temperature: -40°C+85°C; Tolerance: NA; Voltage: NA; Wattage: NA; Weight: NA; Datasheet: Y:\MIS_DATABASE\DATASHEETS\MISC\SWITCHES\TDAXX-SER.PDF
TP52-TP60 = TESTPOINT: TESTPOINT CIR 40 SMD; Chkd/date: MAZHAR/190505; Crtd /date: MAZHAR/190505; Distributor_name: NA; Distributor_part_number: NA; Footprint Path: Y:\MIS_DATABASE\Library\ALTIUM_TOOL\PCB_FOOTPRINTS\Altium_Footprint_Lib.PcbLib; Height: NA; Library Path: Y:\MIS_DATABASE\Library\ALTIUM_TOOL\SCHEMATICS_PARTS\MS_DISCRETE_Library.schlib; MECHANICAL 3D STEP FILE: NA; Mfr_name: LOCAL; Mistral Part No: 130009030933; Package: SMD; Project: RAINIER-3; RoHS: NA; Temperature: NA; Tolerance: NA; Voltage: NA; Wattage: NA; Weight: NA; Datasheet: NA
U31 = ISO7220XD_SOIC8: IC DUAL-CHANNEL 25MBpS DIGITAL ISOLATORS SOIC8; Chkd/date: NAVEED/100715; Crtd /date: VASANTHA/060814; Custom_Duty: 15%; Customs_HS_Code: 85423100; Distributor_name: DIGIKEY; Distributor_part_number: 296-21953-1-ND; Height: 1.75MM; Mfr_name: TEXAS INSTRUMENTS; Mistral Part No: 141014080006-R; Part_type: ICS\MISC; Project: ZK_BIOMETRIC; RoHS: RoHS; Temperature: -40°C+125°C; Tolerance: NA; Voltage: NA; Wattage: NA; Weight: NA; Datasheet: Y:\MIS_DATABASE\DATASHEETS\ICS\POWER\ISO722X.PDF
U32 = ISO7221XD_SOIC8: IC DUAL-CHANNEL DIGITAL ISOLATOR WITH ROBUST EMC SOIC8; Chkd/date: MANIRAJA/111121; Crtd /date: ALVY/101121; Custom_Duty: 15%; Customs_HS_Code: 85423100; Distributor_name: DIGIKEY; Distributor_part_number: 296-ISO6721BQDRQ1CT-ND; Footprint Path: Y:\MIS_DATABASE\Library\ALTIUM_TOOL\PCB_FOOTPRINTS\Altium_Footprint_Lib.PcbLib; Height: 1.75MM; Library Path: Y:\MIS_DATABASE\Library\ALTIUM_TOOL\SCHEMATICS_PARTS\MS_MISC_Library.schlib; Mfr_name: TEXAS INSTRUMENTS; Mistral Part No: 141021110013-R; Package: SOIC8; Part_type: ICS\DIGITAL\ISOLATOR; Project: TI_AM263x_CC_BRD; RoHS: RoHS; Temperature: -40°C+125°C; Tolerance: NA; Voltage: NA; Wattage: NA; Weight: NA; Datasheet: Y:\MIS_DATABASE\DATASHEETS\ICS\MISC\ISO672X-Q1.PDF
Y1 = CRY4_ABM8G: CRY 25.000MHz 8pF SMD; Chkd/date: MANIRAJA/250620; Crtd /date: ALVY/250620; Custom_Duty: 24%; Customs_HS_Code: 85439000; Distributor_name: DIGIKEY; Distributor_part_number: 535-13736-1-ND; Footprint Path: Y:\MIS_DATABASE\Library\ALTIUM_TOOL\PCB_FOOTPRINTS\Altium_Footprint_Lib.PcbLib; Height: 0.60MM; Library Path: Y:\MIS_DATABASE\Library\ALTIUM_TOOL\SCHEMATICS_PARTS\MS_DISCRETE_Library.schlib; Mfr_name: ABRACON CORPORATION; Mfr_part_number: ABM10W-25.0000MHZ-8-K1Z-T3; Mistral Part No: 130020060044-R; Package: SMD; Part_type: CRYSTAL; Project: AM64x_SVB DUT BRD; RoHS: RoHS; Temperature: -40°C+125°C; Tolerance: NA; Voltage: NA; Wattage: NA; Weight: NA; Datasheet: Y:\MIS_DATABASE\DATASHEETS\MISC\CRY_OSC\ABM10W.PDF
U1 = XAM263P4ASOKFZCZ_BGA324: IC SIP AM263P SoC BGA324; Chkd/date: PRADEEP/030124; Crtd /date: PRADEEP/030124; Custom_Duty: 15%; Customs_HS_Code: 85423100; Distributor_name: NA; Distributor_part_number: NA; Footprint Path: Y:\MIS_DATABASE\Library\ALTIUM_TOOL\PCB_FOOTPRINTS\Altium_Footprint_Lib.PcbLib; Height: 1.40MM; MECHANICAL 3D STEP FILE: NA; Mfr_name: TEXAS INSTRUMENTS; Mistral Part No: 141324010001; Package: BGA324; Part_type: ICS\DIGITAL\FPGA; Project: AM263P_CC; RoHS: RoHS; Temperature: NA; Tolerance: NA; Voltage: NA; Wattage: NA; Weight: NA; Datasheet: Y:\MIS_DATABASE\DATASHEETS\ICS\INTERFACE\ZCZ0324A.PDF

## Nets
DGND: C86.2 C171.2 C172.1 C173.2 C177.2 C179.1 C181.1 C183.1 C184.2 C185.2 C186.1 C187.1 J6.3 J6.4 J6.9 LD8.1(CATHODE) LD19.1(CATHODE) Q3.2(S) Q4.2(S) R67.2 R148.2 R149.2 R164.2 R165.2 R166.2 R168.1 R169.1 R170.1 R186.2 R187.2 R188.2 R189.2 R202.2 R203.2 R461.2 U20.8(GND) U26.8(GND) U27.5(GND) U28.4(GND) U30.8(GND) U31.5(GND2) U32.4(GND1) Y1.2(GND1) Y1.4(GND2) ; also on sheet 1 2 3 4 6 7 8 9 10 11 12 13 14 15 16 17 24 25 28 29 30 32 33
VCC3V3_XDS: C180.2 C182.2 U31.1(VCC1) U32.8(VCC2) ; also on sheet 3 17 28
1588_SFD: R3881.2 ; also on sheet 7
CLOCKOUT0: U1.M2(CLKOUT0) ; also on sheet 9
EEPROM_A1: R168.2 U28.2(A1)
EEPROM_A2: R169.2 U28.3(A2)
EEPROM_WP: R167.2 R170.2 U28.7(WP)
EPWM7_A: R3880.1 R3881.1 U1.F4(EPWM7_A)
EPWM7_B: R3876.1 R3877.1 U1.F1(EPWM7_B)
EPWM10_B: R193.1 R3879.1 U1.J3(EPWM10_B)
EPWM11_A: R190.1 R3865.1 U1.H1(EPWM11_A)
FSIRX2_CLK: J6.1 ; also on sheet 13
FSIRX2_CLK/MCAN4_TXD: U1.J2(EPWM9_B) ; also on sheet 13
FSIRX2_DATA0: J6.5 ; also on sheet 13
FSIRX2_DATA0/MCAN5_RXD: U1.G4(EPWM10_A) ; also on sheet 13
FSIRX2_DATA1: J6.7 ; also on sheet 13
FSIRX2_DATA1/MCAN5_TXD: R193.2 ; also on sheet 13
FSITX2_CLK: J6.2 U1.G3(EPWM8_A)
FSITX2_DATA0: J6.6 U1.H2(EPWM8_B)
FSITX2_DATA1: J6.8 ; also on sheet 13
FSITX2_DATA1/MCAN4_RXD: U1.G1(EPWM9_A) ; also on sheet 13
HSEC_EPWM0_A: U1.B2(EPWM0_A) ; also on sheet 6
HSEC_EPWM0_B: U1.B1(EPWM0_B) ; also on sheet 6
HSEC_EPWM1_A: U1.D3(EPWM1_A) ; also on sheet 6
HSEC_EPWM1_B: U1.D2(EPWM1_B) ; also on sheet 6
HSEC_EPWM2_A: U1.C2(EPWM2_A) ; also on sheet 6
HSEC_EPWM2_B: U1.C1(EPWM2_B) ; also on sheet 6
HSEC_EPWM3_A: U1.E2(EPWM3_A) ; also on sheet 2
HSEC_EPWM3_B: U1.E3(EPWM3_B) ; also on sheet 6
HSEC_EPWM4_A: U1.D1(EPWM4_A) ; also on sheet 6
HSEC_EPWM4_B: U1.E4(EPWM4_B) ; also on sheet 6
HSEC_EPWM5_A: U1.F2(EPWM5_A) ; also on sheet 6
HSEC_EPWM5_B: U1.G2(EPWM5_B) ; also on sheet 6
HSEC_EPWM6_A: U1.E1(EPWM6_A) ; also on sheet 6
HSEC_EPWM6_B: U1.F3(EPWM6_B) ; also on sheet 6
HSEC_EPWM7_A: R3880.2 ; also on sheet 6
HSEC_EPWM7_B: R3876.2 ; also on sheet 6
HSEC_EPWM11_A: R190.2 ; also on sheet 6
HSEC_EPWM13_A: R192.2 ; also on sheet 6
HSEC_EPWM13_B: R196.2 ; also on sheet 6
HSEC_EQEP0_A: U1.B14(EQEP0_A) ; also on sheet 6
HSEC_EQEP0_B: U1.A14(EQEP0_B) ; also on sheet 6
HSEC_EQEP0_INDEX: U1.D11(EQEP0_INDEX) ; also on sheet 6
HSEC_EQEP0_STROBE: U1.C12(EQEP0_STROBE) ; also on sheet 6
HSEC_EQEP2_A: U26.6(2B2) ; also on sheet 6
HSEC_EQEP2_B: U26.3(1B2) ; also on sheet 6
HSEC_EQEP2_INDEX: U1.A12(MCAN2_RX) ; also on sheet 6
HSEC_EQEP2_STROBE: U1.B12(MCAN2_TX) ; also on sheet 6
HSEC_EXT_REFCLK0: U1.P2(EXT_REFCLK0) ; also on sheet 6
HSEC_I2C1_SCL: R152.2 U1.D7(I2C1_SCL) ; also on sheet 6
HSEC_I2C1_SDA: R153.2 U1.C8(I2C1_SDA) ; also on sheet 6
HSEC_SDFM0_CLK0: U1.B16(SDFM0_CLK0) ; also on sheet 6
HSEC_SDFM0_CLK1: U1.A16(SDFM0_CLK1) ; also on sheet 6
HSEC_SDFM0_CLK2: U1.B15(SDFM0_CLK2) ; also on sheet 6
HSEC_SDFM0_CLK3: U1.A15(SDFM0_CLK3) ; also on sheet 6
HSEC_SDFM0_D0: U1.D14(SDFM0_D0) ; also on sheet 6
HSEC_SDFM0_D1: U1.D13(SDFM0_D1) ; also on sheet 6
HSEC_SDFM0_D2: U1.C13(SDFM0_D2) ; also on sheet 6
HSEC_SDFM0_D3: U1.C14(SDFM0_D3) ; also on sheet 6
HSEC_SPI0_CLK: R139.1 R150.1 ; also on sheet 6
HSEC_SPI0_CS0: U1.C11(SPI0_CS0) ; also on sheet 6
HSEC_SPI0_D0: R151.1 U1.C10(SPI0_D0) ; also on sheet 6
HSEC_SPI0_D1: U1.B11(SPI0_D1) ; also on sheet 6
HSEC_TCK: R183.2 U30.14(4B1) ; also on sheet 6
HSEC_TDI: R181.2 U30.5(2B1) ; also on sheet 6
HSEC_TDO: R180.2 U30.2(1B1) ; also on sheet 6
HSEC_TMS: R182.2 U30.11(3B1) ; also on sheet 6
I2C0_MUX_OE#: R165.1 U26.15(~{OE})
I2C0_MUX_SEL: R162.2 R164.1 U26.1(S) ; also on sheet 12
I2C0_SCL: R154.2 U26.2(1B1) U28.6(SCL) ; also on sheet 7
I2C0_SDA: R155.2 U26.5(2B1) U28.5(SDA) ; also on sheet 7
ICSSM1_INTn: R195.2 ; also on sheet 15
ICSSM2_PWDN/INTn: R191.2 ; also on sheet 7
JTAG_MUX1_OE#: C178.2 R189.1 U30.15(~{OE})
JTAG_MUX_SEL: R188.1 SW1.1 U30.1(S)
LIN2_RXD: U1.B8(LIN2_RXD) U20.4(1A)
LIN2_TXD: U1.A8(LIN2_TXD) U20.7(2A)
MUX_UART1/LIN_RXD: R143.2 ; also on sheet 9
MUX_UART1/LIN_TXD: R145.2 ; also on sheet 9
OSPI0_RESET_OUT0: R194.2 ; also on sheet 24
OSPI_ERR#: R3865.2 ; also on sheet 24
OSPI_RSTn_R: R3879.2 ; also on sheet 24
PMIC_SAFE_OUT2: Q5.1(G) R202.1 ; also on sheet 6 30
PORZ: R187.1 U1.R2(PORZ) ; also on sheet 6 7 10 11 15 24
RESETz: R185.1 ; also on sheet 10
RSVD_U1: R186.1 U1.U1(RSVD)
RSVD_U3: TP59.1(TP) U1.U3(RSVD)
RSVD_V2: TP60.1(TP) U1.V2(RSVD)
SAFETY_ERRORn: Q20.1(G) TP56.1(TP) U1.D4(SAFETY_ERRORN) ; also on sheet 30
SOC_BOOTMODE2: R150.2 ; also on sheet 11
SOC_BOOTMODE3: R151.2 ; also on sheet 11
SOC_CLK_IN: R176.1 ; also on sheet 9
SOC_CLK_XTAL_IN: C184.1 R178.1 Y1.1
SOC_CLK_XTAL_OUT: C185.1 R179.1 Y1.3
SOC_I2C0_SCL: R135.1 R159.2 U26.4(1A)
SOC_I2C0_SDA: R136.1 R158.2 U26.7(2A)
SOC_I2C2_SCL: R156.2 U1.C7(UART0_RTSN) U27.8(SCL) ; also on sheet 1 12 28
SOC_I2C2_SDA: R157.2 U1.B7(UART0_CTSN) U27.7(SDA) ; also on sheet 1 12 28
SOC_INTn: U20.2(1B1) ; also on sheet 10
SOC_OSPI0_DQS: R118.1 ; also on sheet 24
SOC_OSPI0_LBCLK: R117.1 ; also on sheet 24
SOC_SPI1_CLK: R140.1 ; also on sheet 30
SOC_SPI1_CS0: R144.1 ; also on sheet 30
SOC_SPI1_D0: R141.1 ; also on sheet 30
SOC_SPI1_D1: U1.D9(SPI1_D1) ; also on sheet 30
SOC_TCK: TP52.1(TP) U1.B3(TCK) U30.12(4A)
SOC_TDI: TP53.1(TP) U1.C5(TDI) U30.7(2A)
SOC_TDO: R177.1 TP54.1(TP) U30.4(1A)
SOC_TDO_R: R177.2 U1.C4(TDO)
SOC_TMS: TP55.1(TP) U1.D5(TMS) U30.9(3A)
TMP411_ALERT: R160.2 U27.6(~{ALERT}/~{THERM2})
TMP411_THERM: R161.2 U27.4(~{THERM})
UART0_RXD: U1.A7(UART0_RXD) ; also on sheet 17
UART0_TXD: U1.A6(UART0_TXD) ; also on sheet 17
UART2_MUX_SEL: R62.2 R67.1 U20.1(S) ; also on sheet 12
UART2_RXD_HSEC: U20.3(1B2) ; also on sheet 6
UART2_TXD_HSEC: U20.6(2B2) ; also on sheet 6
USER_LED0: R146.2 U20.5(2B1)
USER_LED1: R147.2 R3877.2
VMAIN: R137.1 R138.1 R201.1 ; also on sheet 1 4 10 14 29
VSYS_3V3_LDO1: C86.1 C171.1 C173.1 C177.1 C178.1 C179.2 C181.2 C187.2 J6.10 R62.1 R152.1 R153.1 R154.1 R155.1 R156.1 R157.1 R158.1 R159.1 R162.1 R167.1 R180.1 R181.1 R182.1 R183.1 R184.1 R200.1 R3832.1 U20.16(VCC) U26.16(VCC) U28.8(VCC) U30.16(VCC) U31.8(VCC2) U32.1(VCC1) ; also on sheet 1 6 7 9 10 11 12 13 14 15 16 17 24 28 29 30 32 33
VSYS_3V3_LDO2: C172.2 R160.1 R161.1 U27.1(V+) ; also on sheet 1 9 12 13 25 30
VSYS_MON: C186.2 R201.2 R203.1 TP57.1(TP) U1.U2(VSYS_MON)
WARMRESETn: R185.2 TP58.1(TP) U1.C3(WARMRSTN) ; also on sheet 12 25
XDS110_TCK: U31.3(INB) ; also on sheet 17
XDS110_TCK_ISO: R198.1 U30.13(4B2)
XDS110_TDI: U32.7(INA) ; also on sheet 17
XDS110_TDI_ISO: R199.1 U30.6(2B2)
XDS110_TDO: U32.6(OUTB) ; also on sheet 17
XDS110_TDO_ISO: U30.3(1B2) U32.3(INB)
XDS110_TMS: U31.2(INA) ; also on sheet 17
XDS110_TMS_ISO: R197.1 U30.10(3B2)
XDS_GND: C180.1 C182.1 C183.2 U31.4(GND1) U32.5(GND2) ; also on sheet 3 17 28
XTAL_IN: R176.2 R178.2 U1.T1(XTAL_XI)
XTAL_OUT: R179.2 U1.R1(XTAL_XO)
N32781982: R166.1 U26.9(3A) U26.12(4A)
N32843337: R184.2 SW1.2
N33056127: LD6.2(ANODE) R137.2
N33056129: LD6.1(CATHODE) Q3.3(D)
N33056157: Q3.1(G) R146.1 R148.1
N33200463: R139.2 U1.A11(SPI0_CLK)
N33200513: R140.2 U1.A10(SPI1_CLK)
N33277398: Q4.1(G) R147.1 R149.1
N33277404: LD7.2(ANODE) R138.2
N33277419: LD7.1(CATHODE) Q4.3(D)
N33334993: R163.1 U27.2(D+)
N33879615: R143.1 U1.A9(LIN1_RXD)
N33879618: R145.1 U1.B9(LIN1_TXD)
N33885275: R199.2 U32.2(OUTA)
N33885316: R197.2 U31.7(OUTA)
N33885344: R198.2 U31.6(OUTB)
N34075368: R163.2 U27.3(D-)
N34422674: R135.2 U1.A13(I2C0_SCL)
N34422702: R136.2 U1.B13(I2C0_SDA)
N34549994: R144.2 U1.C9(SPI1_CS0)
N34801624: R191.1 U1.K2(EPWM12_A)
N34801627: R192.1 U1.K4(EPWM13_A)
N34801685: R194.1 U1.J1(EPWM11_B)
N34801688: R195.1 U1.J4(EPWM12_B)
N34801691: R196.1 U1.K3(EPWM13_B)
N34820524: Q5.2(S) R200.2
N34820530: LD8.2(ANODE) Q5.3(D)
N35059517: R141.2 U1.B10(SPI1_D0)
N35329968: R117.2 U1.L3(UART1_RXD)
N35329989: R118.2 U1.M3(UART1_TXD)
N35395797: R461.1 U20.15(~{OE})
N35654609: Q20.2(S) R3832.2
N35654631: LD19.2(ANODE) Q20.3(D)

Not connected (* = marked no-connect by the designer): U20 9(3A)* 10(3B2)* 11(3B1)* 12(4A)* 13(4B2)* 14(4B1)*; U26 10(3B2)* 11(3B1)* 13(4B2)* 14(4B1)*; U28 1(NC)*

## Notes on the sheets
sheet 26
- SOC-IO Interfaces
- USER LEDs
- CAD Note: Place 0-ohm
  resistors as close To
  SoC as possible.
- RED
- GREEN
- BOOTMODES
- I2C Pull-ups
- Note: 10K resistors are used to
  isolate the BOOTMODE control logic
  after the value is latched.
- Temperature Sensor
- I2C0 MUX/DEMUX
- I2C0 - 1:2  MUX
- Note: D+ and D- Shorted as
  TEMPCAL is not used
- I2C Addr: 0X4C
- SEL
- CONDITION
- FUNCTION
- PCB Note: Place Close To SOC
- LOW
- I2C0 SELECTED
- A-->B1 port
- HIGH
- HSEC EQEP selected
- A-->B2 port
- Board ID EEPROM
- UART2 MUX
- UART2 MUX
- SEL
- CONDITION
- FUNCTION
- EEPROM Address - 0x50
- LOW
- GPIOs SELECTED
- A-->B1 port
- HIGH
- HSEC UART2 selected
- A-->B2 port
sheet 27
- SOC JTAG, RESET and CLKS
- JTAG MUX
- VSYS_MON
- JTAG - 1:2  MUX
- SW1.1
- CONDITION
- FUNCTION
- LOW
- HSEC EMU selected
- A-->B1 port [EXTERNAL EMU]
- HIGH
- XDS110 selected
- A-->B2 port [ON Board EMU]
- 4.75V(95% of 5V) to 0.945V(0.9+5%)
- ISOLATION FOR XDS110
- PMIC_SAFETY_ERROR
- CAD NOTE: PLACE TERMINATION RESISTORS CLOSER TO SOC AS MUCH AS POSSIBLE
- SOC Clock
- RED
- NOTE: Load CAP to be discussed
- SAFETY_ERROR
- FSI Header
- RED
